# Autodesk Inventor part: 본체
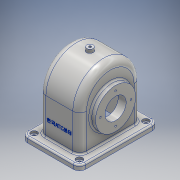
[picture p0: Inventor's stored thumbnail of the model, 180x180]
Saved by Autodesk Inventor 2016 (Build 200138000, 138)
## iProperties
Created: 2018-11
Part Number: 본체
Material: 알루미늄 6061
Document SubType Name: Modeling
Designer: user
Mass: 1141.02 g
Surface Area: 1182.34 cm^2
Volume: 422.6 cm^3
Density: 2.7 g/cm^3
Appearance: 알루미늄 - 평지
Author: user
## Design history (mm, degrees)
sketch "스케치1"
  geometry: C1 r 58 at (0, 0); 1 further point
  constraints: 1 centre point, 1 coincident
  dimensions: "d1" = 116 diameter of C1
extrude "돌출1" new body sketch "스케치1" stored distance "d2" = 77; taper "d3" = 0 deg
sketch "스케치2"
  geometry: L1 (-38.5, 58)-(-38.5, -58) reference; L2 (38.5, -58)-(38.5, 58) reference; L3 (-38.5, 58)-(38.5, 58); L4 (38.5, 58)-(38.5, -58); L5 (38.5, -58)-(-38.5, -58); L6 (-38.5, -58)-(-38.5, 58); 1 further point
  constraints: 8 end point, 2 parallel, 1 horizontal, 1 perpendicular
extrude "돌출2" join sketch "스케치2" distance "d4" = 78; taper "d5" = 0 deg
sketch "스케치3"
  geometry: L1 (38.5, 58)-(-38.5, 58) reference; L2 (-38.5, 58)-(-38.5, -58) reference; L3 (-38.5, -58)-(38.5, -58) reference; L4 (38.5, -58)-(38.5, 58) reference; L5 (55, -75)-(-55, -75); L6 (-55, -75)-(-55, 75); L7 (-55, 75)-(55, 75); L8 (55, 75)-(55, -75); L9 (55, -75)-(-55, 75); L10 (-55, -75)-(55, 75); 1 further point
  constraints: 12 end point, 2 midpoint, 2 parallel, 1 horizontal, 1 perpendicular
  dimensions: "d6" = 110 distance of L6.end L7.end; "d7" = 150 distance of L5.end L6.end
  node "투영된 루프1"
feature "쉘1" dims "d8" = 6, "d77" = 5
extrude "돌출3" join sketch "스케치3" distance "d9" = 10; taper "d10" = 0 deg
node "작업 평면1"
sketch "스케치4"
  geometry: L1 (38.5, 58)-(-38.5, 58) reference; L2 (38.5, -58)-(38.5, 58) reference; L3 (38.5, -58)-(-38.5, -58) reference; L4 (-38.5, 58)-(-38.5, -58) reference; L5 (-38.5, -58)-(-38.5, 58) reference; L6 (38.5, -58)-(-38.5, -58) reference; L7 (38.5, 58)-(38.5, -58) reference; L8 (-38.5, 58)-(38.5, 58) reference; L9 (55, -75)-(-55, -75) reference; L10 (-55, -75)-(-55, 75) reference; L11 (-55, 75)-(55, 75) reference; L12 (55, 75)-(55, -75) reference; C1 r 6 at (0, 0); 1 further point
  constraints: 1 centre point, 1 coincident
  dimensions: "d12" = 12 diameter of C1
extrude "돌출4" join sketch "스케치4" stored distance "d13" = 5; taper "d14" = 5 deg
sketch "스케치5"
  geometry: L1 (68, -58)-(68, 58) reference; L2 (0, 58)-(68, 58) reference; L3 (0, -58)-(68, -58) reference; L4 (78, -75)-(78, 75) reference; C1 r 38 at (13, 0); A1 r 58 centre (0, 0) between (0, 58) and (0, -58) reference; A2 r 58 centre (0, 0) between (0, 58) and (0, -58) reference; 2 further points
  constraints: 1 centre point, 1 horizontal alignment, 1 point on circle
  dimensions: "d17" = 76 diameter of C1; "d18" = 65 distance from line of L4 C1.centre
extrude "돌출5" join sketch "스케치5" distance "d19" = 10; taper "d20" = 0 deg
sketch "스케치6"
  geometry: C1 r 38 at (-13, 0) reference; 1 further point
extrude "돌출6" join sketch "스케치6" distance "d21" = 5; taper "d22" = 0 deg
sketch "스케치7"
  geometry: L1 (33.5, 0)-(-33.5, 0) reference; L2 (33.5, 0)-(33.5, -78) reference; L3 (-33.5, -78)-(33.5, -78) reference; L4 (-33.5, 0)-(-33.5, -78) reference; L5 (33.5, 0)-(-33.5, 0) reference; L6 (-33.5, 0)-(-33.5, 0) reference; L7 (33.5, 0)-(-33.5, 0) reference; L8 (33.5, 0)-(33.5, 0) reference; L9 (33.5, 0)-(33.5, 52) reference; L10 (-33.5, 52)-(-33.5, 0) reference; L11 (43.5, -51)-(43.5, 25) reference; L12 (19.5, 15)-(19.5, -13); L13 (38.5, 0)-(38.5, -68) reference; L14 (19.5, 15)-(33.5, 26.747); L15 (19.5, -13)-(33.5, -13); L16 (33.5, 26.747)-(33.5, -13); L17 (33.5, 0)-(33.5, -78) reference; 1 further point
  constraints: 8 end point, 2 point on line, 1 collinear, 1 parallel, 1 perpendicular
  dimensions: "d23" = 28 distance of L12.start L12.end; "d25" = 24 distance between parallel lines of L12 L11; "d26" = 50 deg angle of L14 L12
revolve "회전1" sketch "스케치7" stored, may be unused: angle "d27" = 90 deg
fillet "모깎기1" dims "d28" = 3
sketch "스케치8"
  geometry: C1 r 38 at (0, 0) reference; 2 further points
  constraints: 1 coincident
hole "구멍1" sketch "스케치8" at (0, 0) diameter "d29" = 40; stored, may be unused: countersink angle "d33" = 90 deg, drill point angle "d35" = 118 deg; dims "d30" = 6, "d31" = 4, "d32" = 2, "d34" = 8
sketch "스케치9"
  geometry: C1 r 6 at (0, 0) reference; 2 further points
  constraints: 1 coincident
hole "구멍2" sketch "스케치9" at (0, 0) diameter "d36" = 4.459; stored, may be unused: countersink angle "d40" = 90 deg, drill point angle "d42" = 118 deg; dims "d37" = 30, "d38" = 4, "d39" = 2, "d41" = 12.8
fillet "모깎기2" dims "d43" = 13
fillet "모깎기3" dims "d44" = 3
fillet "모깎기4" dims "d45" = 8
fillet "모깎기5" dims "d46" = 12
fillet "모깎기6" dims "d47" = 3
sketch "스케치10"
  geometry: L1 (43, 75)-(-43, 75) reference; L2 (55, -63)-(55, 63) reference; L3 (-43, -75)-(43, -75) reference; L4 (-55, 63)-(-55, -63) reference; L5 (25.5, 52)-(-25.5, 52) reference; L6 (-33.5, 44)-(-33.5, -44) reference; L7 (-25.5, -52)-(25.5, -52) reference; L8 (33.5, -44)-(33.5, 44) reference; A1 r 12 centre (-43, 63) between (-43, 75) and (-55, 63) reference; A2 r 12 centre (43, 63) between (55, 63) and (43, 75) reference; A3 r 12 centre (43, -63) between (43, -75) and (55, -63) reference; A4 r 12 centre (-43, -63) between (-55, -63) and (-43, -75) reference; A5 r 8 centre (-25.5, 44) between (-25.5, 52) and (-33.5, 44) reference; A6 r 8 centre (-25.5, -44) between (-33.5, -44) and (-25.5, -52) reference; A7 r 8 centre (25.5, -44) between (25.5, -52) and (33.5, -44) reference; A8 r 8 centre (25.5, 44) between (33.5, 44) and (25.5, 52) reference; 5 further points
  constraints: 4 coincident
hole "구멍3" sketch "스케치10" at (-43, 63), (43, 63), (43, -63), (-43, -63) diameter "d48" = 5; stored, may be unused: countersink angle "d52" = 90 deg, drill point angle "d54" = 118 deg; dims "d49" = 30, "d50" = 12, "d51" = 4, "d53" = 12.8
sketch "스케치11"
  geometry: C1 r 20 at (0, 0) reference; C2 r 38 at (0, 0) reference; A1 r 29 centre (0, 0) between (-29, 0) and (0, 29); 3 further points
  constraints: 4 point on circle, 1 centre point, 1 coincident
  dimensions: "d55" = 58 diameter of A1
hole "구멍4" sketch "스케치11" at (-29, 0), (0, 29), (0, -29), (29, 0) diameter "d56" = 3.242; stored, may be unused: countersink angle "d60" = 90 deg, drill point angle "d62" = 118 deg; dims "d57" = 8, "d58" = 19.05, "d59" = 4.775, "d61" = 10
sketch "스케치12"
  geometry: L1 (0, 0)-(0, 68) reference; L2 (0, 0)-(51, 0) reference; L3 (51, 68)-(51, 0) reference; L4 (0, 68)-(51, 68) reference; L5 (-17.5, -3)-(68.5, -3) reference; L6 (-17.5, -10)-(-17.5, -3) reference; L7 (-17.5, -10)-(68.5, -10) reference; L8 (68.5, -3)-(68.5, -10) reference; L9 (-13, 0)-(0, 0) reference; L10 (0, 0)-(0, 68) reference; L11 (-13, 68)-(0, 68) reference; L12 (-13, 68)-(-13, 0) reference; 2 further points
  constraints: 1 other
  dimensions: "d64" = 38.5 distance from line of L12 point (25.5, 30); "d65" = 40 distance from line of L7 point (25.5, 30)
feature "엠보싱1" sketch "스케치12" dims "d3" = 0, "d6" = 110, "d7" = 150, "d66" = 0.5, "d67" = 0
sketch "스케치13"
  geometry: C1 r 20 at (0, 0) reference; C2 r 38 at (0, 0) reference; A1 r 29 centre (0, 0) between (29, 0) and (0, -29); 3 further points
  constraints: 4 point on circle, 1 centre point, 1 coincident
  dimensions: "d68" = 58 diameter of A1
hole "구멍5" sketch "스케치13" at (29, 0), (0, -29), (0, 29), (-29, 0) diameter "d69" = 3.242; stored, may be unused: countersink angle "d73" = 90 deg, drill point angle "d75" = 118 deg; dims "d70" = 8, "d71" = 4, "d72" = 2, "d74" = 10
fillet "모깎기7" dims "d76" = 3
node "솔리드1"
node "투영된 루프2"
node "투영된 루프3"
node "투영된 루프4"
node "투영된 루프5"
node "투영된 루프6"
node "투영된 루프7"
node "투영된 루프8"
node "투영된 루프9"
node "투영된 루프10"
node "투영된 루프11"
node "투영된 루프12"
node "투영된 루프13"
node "투영된 루프14"
other parameters: "d11" = -142
